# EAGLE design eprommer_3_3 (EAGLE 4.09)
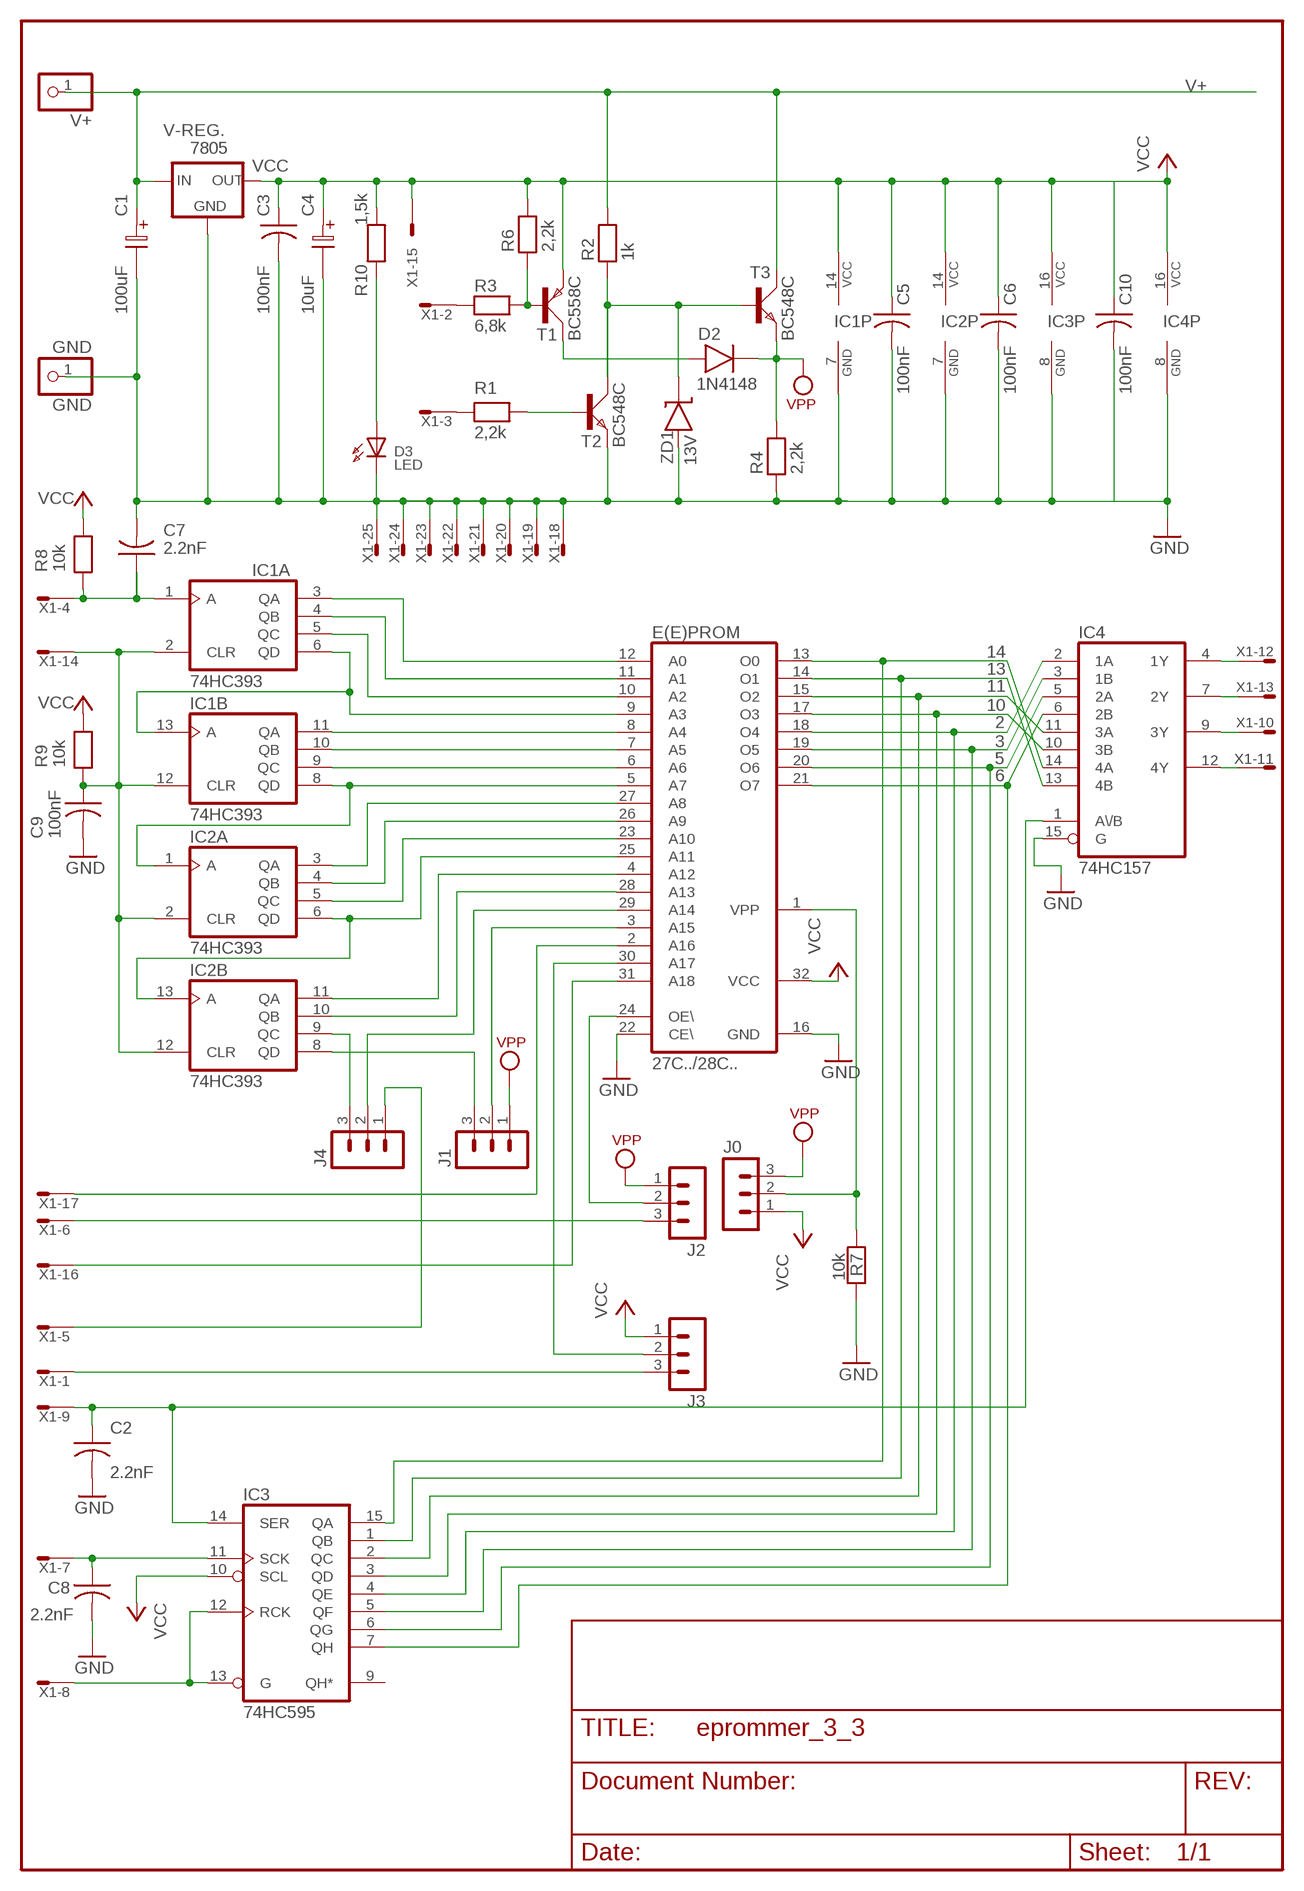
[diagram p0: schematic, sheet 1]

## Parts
C1  100uF  ELC-2,5  [ES-2,5]
C2  2.2nF  CAP-2,5  [C-2,5]
C3  100nF  CAP-2,5  [C-2,5]
C4  10uF  ELC-2,5  [ES-2,5]
C5  100nF  CAP-2,5  [C-2,5]
C6  100nF  CAP-2,5  [C-2,5]
C7  2.2nF  CAP-2,5  [C-2,5]
C8  2.2nF  CAP-2,5  [C-2,5]
C9  100nF  CAP-2,5  [C-2,5]
C10  100nF  CAP-2,5  [C-2,5]
D2  1N4148  DIODE-7,5  [D-7,5]
D3  LED  LED5  [LED5]
E(E)PROM  27C../28C..  27C4001D  [DIL32]
GND  GND  PINHD-1X1  [1X01]
IC1  74HC393  74393  [DIL14]
IC2  74HC393  74393  [DIL14]
IC3  74HC595  74595  [DIL16]
IC4  74HC157  74157  [DIL16]
J0  MA03-1  [MA03-1]
J1  MA03-1  [MA03-1]
J2  MA03-1  [MA03-1]
J3  MA03-1  [MA03-1]
J4  MA03-1  [MA03-1]
R1  2,2k  RESEU-7,5  [R-7,5]
R2  1k  RESEU-7,5  [R-7,5]
R3  6,8k  RESEU-7,5  [R-7,5]
R4  2,2k  RESEU-7,5  [R-7,5]
R6  2,2k  RESEU-7,5  [R-7,5]
R7  10k  RESEU-7,5  [R-7,5]
R8  10k  RESEU-7,5  [R-7,5]
R9  10k  RESEU-7,5  [R-7,5]
R10  1,5k  RESEU-7,5  [R-7,5]
T1  BC558C  BC557  [SOT54A]
T2  BC548C  BC547  [SOT54A]
T3  BC548C  BC547  [SOT54A]
V+  PINHD-1X1  [1X01]
V-REG.  7805  78XXS  [78XXS]
X1  M25HPS  [M25HP]
ZD1  13V  ZDIO-7,5  [D-7,5]

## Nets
A16: E(E)PROM.2(A16) X1.17(-17:M)
A17: J3.3 X1.1(-1:M)
A18/P: E(E)PROM.31(A18) X1.16(-16:M)
A/B_DATA: C2.1 IC3.14(SER) IC4.1(A\/B) X1.9(-9:M)
CLR_ADR: C9.1 IC1.2(A:CLR) IC1.12(B:CLR) IC2.2(A:CLR) IC2.12(B:CLR) R9.1 X1.14(-14:M)
D2/D3: IC4.7(2Y) X1.13(-13:M)
GND: C1.2 C2.2 C3.2 C4.2 C5.2 C6.2 C7.2 C8.2 C9.2 C10.2 D3.K E(E)PROM.16(GND) E(E)PROM.22(CE\) GND.1 IC1.7(P:GND) IC2.7(P:GND) IC3.8(GND) IC4.8(GND) IC4.15(G) R4.1 R7.1 T2.E V-REG..GND X1.18(-18:M) X1.19(-19:M) X1.20(-20:M) X1.21(-21:M) X1.22(-22:M) X1.23(-23:M) X1.24(-24:M) X1.25(-25:M) ZD1.1(A)
IC: E(E)PROM.8(A4) IC1.11(B:QA)
INC_ADR: C7.1 IC1.1(A:A) R8.1 X1.4(-4:M)
LOW->5V: R3.1 X1.2(-2:M)
LOW->12V: R1.1 X1.3(-3:M)
N$1: E(E)PROM.12(A0) IC1.3(A:QA)
N$2: E(E)PROM.11(A1) IC1.4(A:QB)
N$3: E(E)PROM.10(A2) IC1.5(A:QC)
N$4: E(E)PROM.9(A3) IC1.6(A:QD) IC1.13(B:A)
N$5: IC2.9(B:QC) J4.3
N$6: E(E)PROM.7(A5) IC1.10(B:QB)
N$7: E(E)PROM.6(A6) IC1.9(B:QC)
N$8: E(E)PROM.5(A7) IC1.8(B:QD) IC2.1(A:A)
N$9: E(E)PROM.27(A8) IC2.3(A:QA)
N$10: E(E)PROM.26(A9) IC2.4(A:QB)
N$11: E(E)PROM.23(A10) IC2.5(A:QC)
N$12: E(E)PROM.25(A11) IC2.6(A:QD) IC2.13(B:A)
N$13: E(E)PROM.4(A12) IC2.11(B:QA)
N$14: E(E)PROM.29(A14) J4.2
N$15: E(E)PROM.20(O6) IC3.6(QG) IC4.5(2A)
N$16: E(E)PROM.28(A13) IC2.10(B:QB)
N$17: IC2.8(B:QD) J1.3
N$18: E(E)PROM.30(A17) J3.2
N$19: R3.2 R6.1 T1.B
N$20: C8.1 IC3.11(SCK) X1.7(-7:M)
N$21: IC4.4(1Y) X1.12(-12:M)
N$22: IC4.12(4Y) X1.11(-11:M)
N$23: E(E)PROM.13(O0) IC3.15(QA) IC4.14(4A)
N$24: E(E)PROM.14(O1) IC3.1(QB) IC4.13(4B)
N$25: E(E)PROM.15(O2) IC3.2(QC) IC4.11(3A)
N$26: E(E)PROM.17(O3) IC3.3(QD) IC4.10(3B)
N$27: E(E)PROM.18(O4) IC3.4(QE) IC4.2(1A)
N$28: E(E)PROM.19(O5) IC3.5(QF) IC4.3(1B)
N$31: R1.2 T2.B
N$32: D2.1(A) T1.C
N$35: E(E)PROM.21(O7) IC3.7(QH) IC4.6(2B)
N$38: R2.1 T2.C T3.B ZD1.2(K)
N$46: D3.A R10.1
N$48: IC4.9(3Y) X1.10(-10:M)
N$49: E(E)PROM.24(OE\) J2.2
N$50: J2.3 X1.6(-6:M)
PGM: E(E)PROM.3(A15) J1.2
PGM/WE: J4.1 X1.5(-5:M)
RCK/G: IC3.12(RCK) IC3.13(G) X1.8(-8:M)
V+: C1.1 R2.2 T3.C V+.1 V-REG..IN
VCC: C3.1 C4.1 C5.1 C6.1 C10.1 E(E)PROM.32(VCC) IC1.14(P:VCC) IC2.14(P:VCC) IC3.10(SCL) IC3.16(VCC) IC4.16(VCC) J0.1 J3.1 R6.2 R8.2 R9.2 R10.2 T1.E V-REG..OUT X1.15(-15:M)
VPP: D2.2(K) J0.3 J1.1 J2.1 R4.2 T3.E
VPP_EP: E(E)PROM.1(VPP) J0.2 R7.2
Unconnected: IC3.9(QH*) X1.G1(-G:G1) X1.G2(-G:G2)

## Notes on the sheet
- 14
- 13
- 11
- 10
- 2
- 3
- 5
- 6

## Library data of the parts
C1 C4 = DISCRETE:ELC-2,5
C2 C3 C5-C10 = DISCRETE:CAP-2,5
D2 = DISCRETE:DIODE-7,5
D3 = LED:LED5
E(E)PROM = MEMNEC:27C4001D
GND V+ = PINHEAD:PINHD-1X1
IC1 IC2 = 74XX:74393
IC3 = 74XX:74595
IC4 = 74XX:74157
J0 J1-J4 = CON-LSTB:MA03-1
R1-R4 R6-R10 = DISCRETE:RESEU-7,5
T1 = TRANS-SM:BC557
T2 T3 = TRANS-SM:BC547
V-REG. = V-REG:78XXS
X1 = SUBD-A:M25HPS
ZD1 = DISCRETE:ZDIO-7,5

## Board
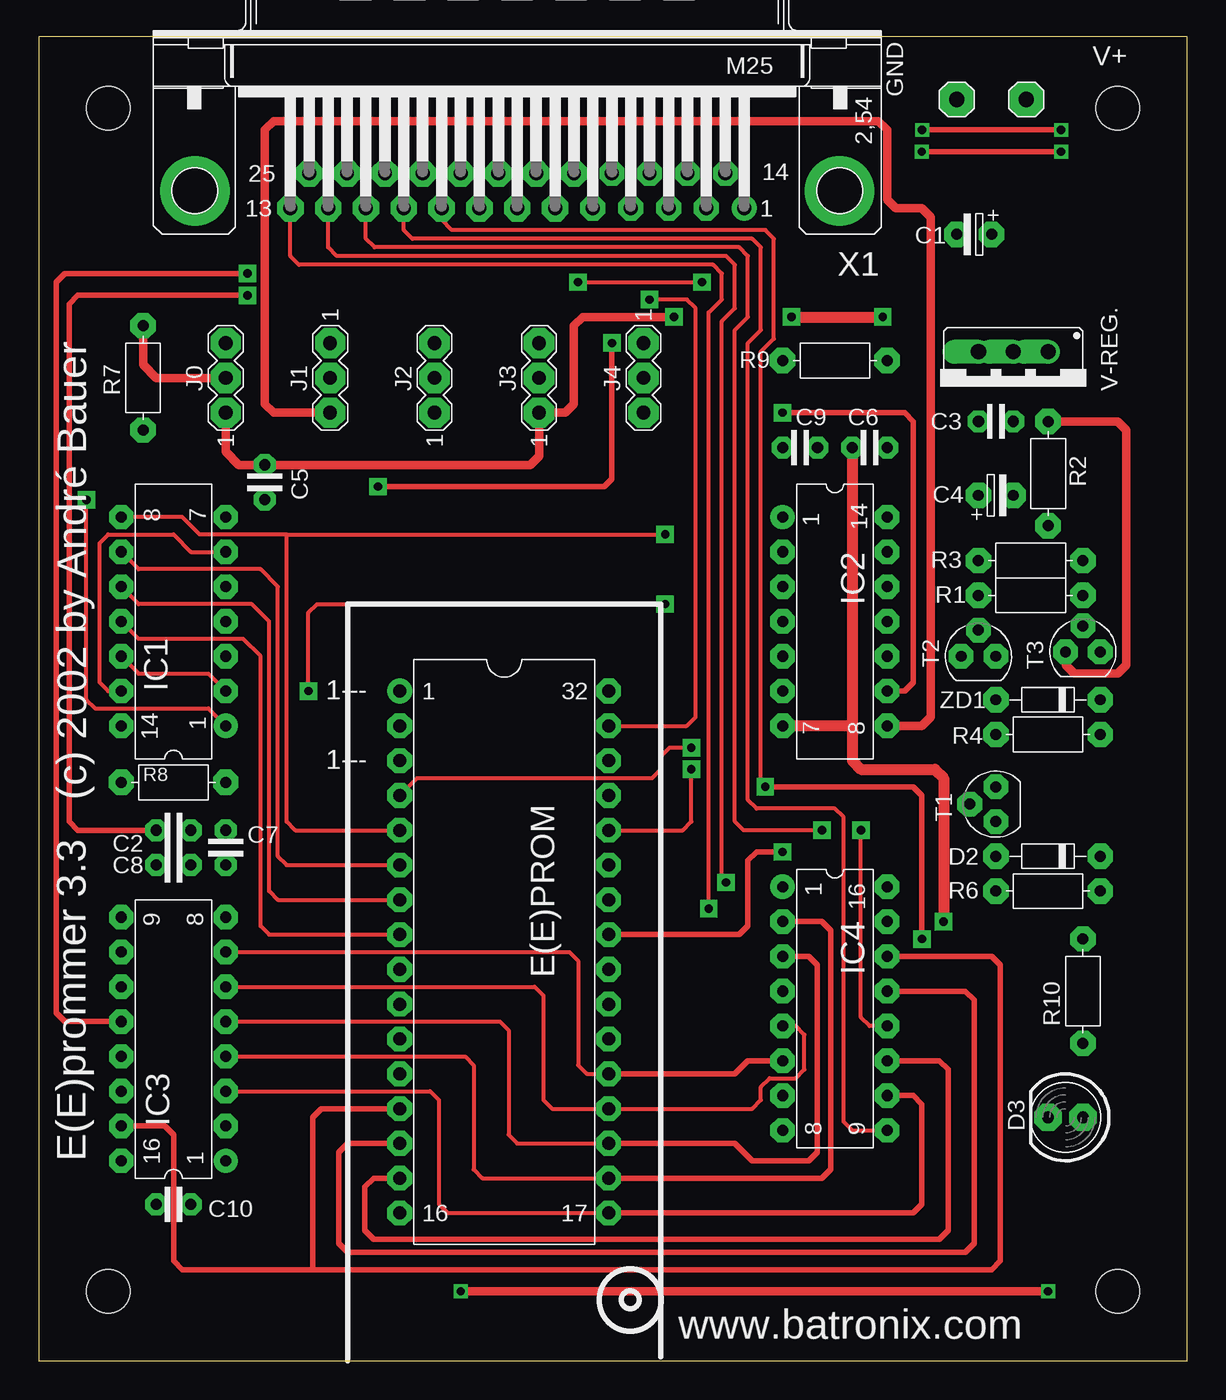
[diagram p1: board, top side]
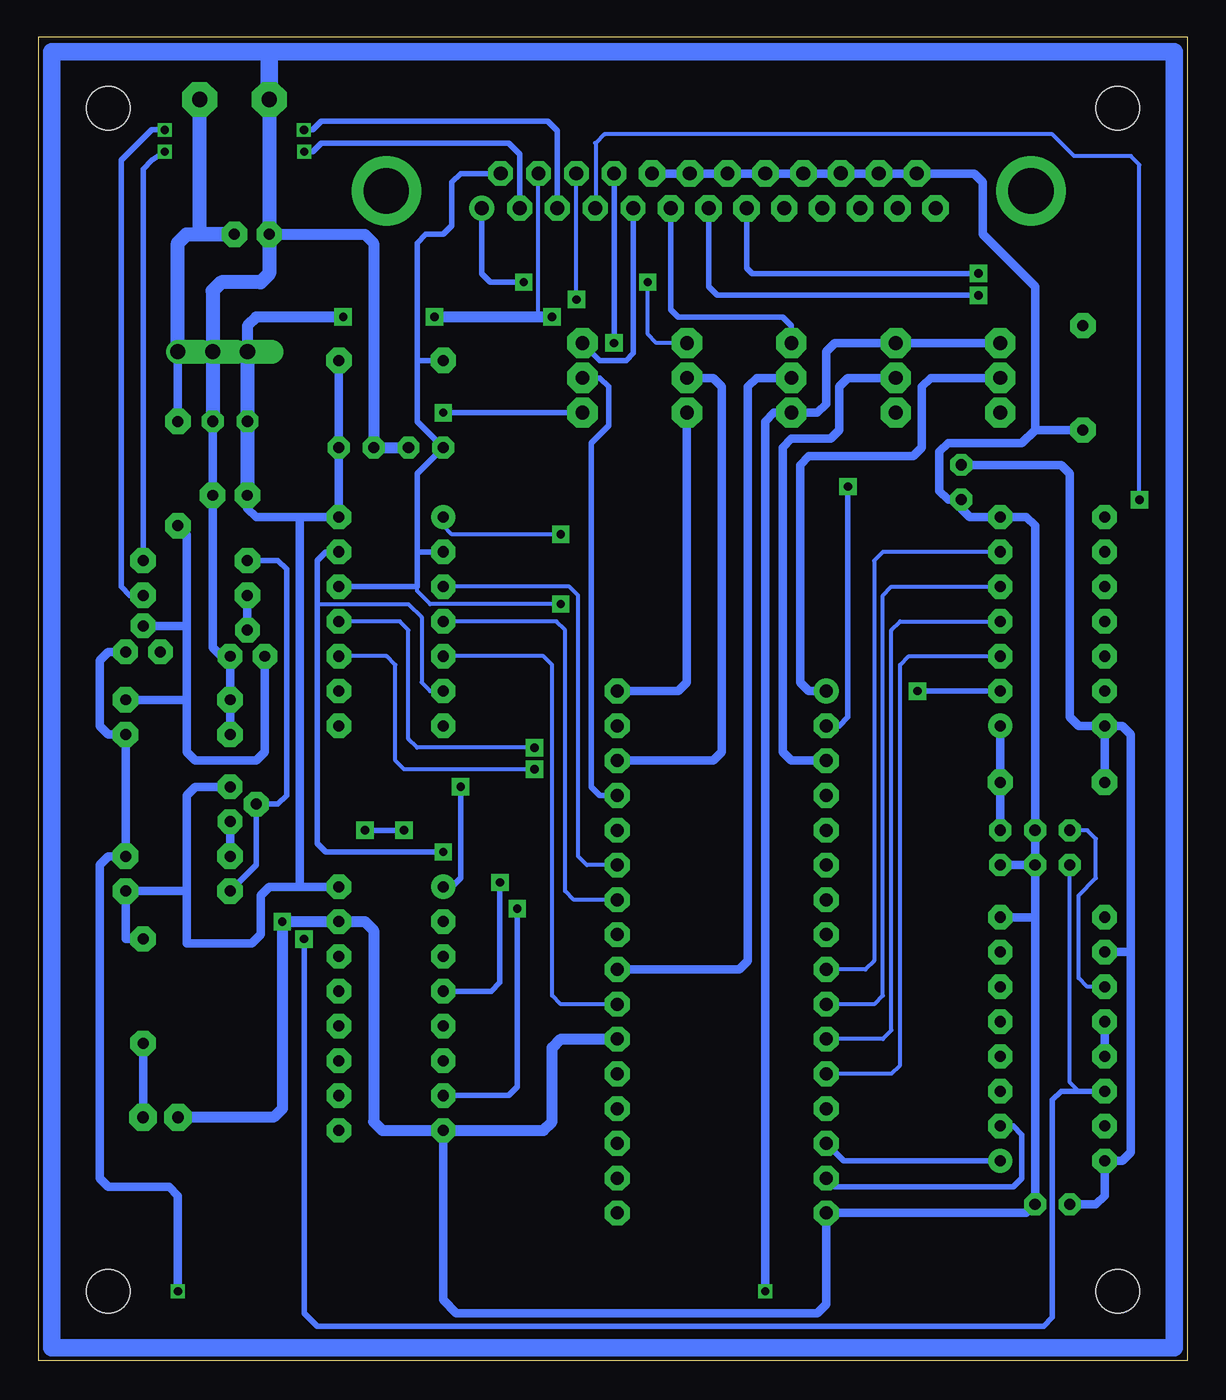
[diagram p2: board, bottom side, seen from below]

Size 83.82 x 96.67 mm. Coordinates in mm from the lower left corner, seen from the top.
Outline: 0,96.67 0,0 83.82,0 83.82,96.67 0,96.67
Copper layers used: Top, Bottom
Holes 3.2 mm at 5.08,91.43 78.73,91.43 5.08,5.07 78.73,5.07

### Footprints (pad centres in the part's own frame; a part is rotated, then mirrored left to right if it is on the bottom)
ES-2,5 = drill 0.8 pad 1.85 octagon: 1 -1.27,0; 2 1.27,0
C-2,5 = drill 0.813 pad 1.6 octagon: 1 -1.27,0; 2 1.27,0
D-7,5 = drill 0.8 pad 1.85 octagon: 1 -3.81,0; 2 3.81,0
LED5 = drill 0.85 pad 2 octagon: A -1.27,0; K 1.27,0
DIL32 = drill 0.95 pad 1.8 round: 1 -19.05,-7.62 | drill 0.95 pad 1.8 octagon: 2 -16.51,-7.62; 3 -13.97,-7.62; 4 -11.43,-7.62; 5 -8.89,-7.62; 6 -6.35,-7.62; 7 -3.81,-7.62; 8 -1.27,-7.62; 9 1.27,-7.62; 10 3.81,-7.62; 11 6.35,-7.62; 12 8.89,-7.62; 13 11.43,-7.62; 14 13.97,-7.62; 15 16.51,-7.62; 16 19.05,-7.62; 17 19.05,7.62; 18 16.51,7.62; 19 13.97,7.62; 20 11.43,7.62; 21 8.89,7.62; 22 6.35,7.62; 23 3.81,7.62; 24 1.27,7.62; 25 -1.27,7.62; 26 -3.81,7.62; 27 -6.35,7.62; 28 -8.89,7.62; 29 -11.43,7.62; 30 -13.97,7.62; 31 -16.51,7.62; 32 -19.05,7.62
1X01 = drill 1.016 pad 2.54 octagon: 1 0,0
DIL14 = drill 0.813 pad 1.778 round: 1 -7.62,-3.81 | drill 0.813 pad 1.778 octagon: 2 -5.08,-3.81; 3 -2.54,-3.81; 4 0,-3.81; 5 2.54,-3.81; 6 5.08,-3.81; 7 7.62,-3.81; 8 7.62,3.81; 9 5.08,3.81; 10 2.54,3.81; 11 0,3.81; 12 -2.54,3.81; 13 -5.08,3.81; 14 -7.62,3.81
DIL16 = drill 0.813 pad 1.778 round: 1 -8.89,-3.81 | drill 0.813 pad 1.778 octagon: 2 -6.35,-3.81; 3 -3.81,-3.81; 4 -1.27,-3.81; 5 1.27,-3.81; 6 3.81,-3.81; 7 6.35,-3.81; 8 8.89,-3.81; 9 8.89,3.81; 10 6.35,3.81; 11 3.81,3.81; 12 1.27,3.81; 13 -1.27,3.81; 14 -3.81,3.81; 15 -6.35,3.81; 16 -8.89,3.81
MA03-1 = drill 1 pad 2.2 octagon: 1 -2.54,0; 2 0,0; 3 2.54,0
R-7,5 = drill 0.8 pad 1.85 octagon: 1 -3.81,0; 2 3.81,0
SOT54A = drill 0.8 pad 1.8 octagon: B 0,1.905; C -1.27,0; E 1.27,0
78XXS = drill 1.1 pad 1.75 offset: GND 0,-2.54; IN -2.54,-2.54; OUT 2.54,-2.54
M25HP = drill 1.016 pad 1.8 round: 1 -16.561,1.27 | drill 1.016 pad 1.8 octagon: 2 -13.792,1.27; 3 -11.049,1.27; 4 -8.28,1.27; 5 -5.512,1.27; 6 -2.769,1.27; 7 0,1.27; 8 2.769,1.27; 9 5.512,1.27; 10 8.28,1.27; 11 11.049,1.27; 12 13.792,1.27; 13 16.561,1.27; 14 -15.189,-1.27; 15 -12.421,-1.27; 16 -9.652,-1.27; 17 -6.909,-1.27; 18 -4.14,-1.27; 19 -1.372,-1.27; 20 1.372,-1.27; 21 4.14,-1.27; 22 6.909,-1.27; 23 9.652,-1.27; 24 12.421,-1.27; 25 15.189,-1.27 | drill 3.302 pad 5.08 round: G1 -23.52,0; G2 23.52,0

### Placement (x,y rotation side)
C1  68.26,82.23 180 top
C2  9.84,36.19 0 top
C3  69.84,68.57 0 top
C4  69.84,63.18 0 top
C5  16.5,64.13 270 top
C6  60.64,66.67 180 top
C7  13.65,37.46 270 top
C8  9.84,38.73 0 top
C9  55.56,66.67 0 top
C10  9.84,11.42 0 top
D2  73.66,36.82 0 top
D3  74.92,17.77 180 top
E(E)PROM  33.97,29.84 270 top
GND  66.99,92.07 0 top
IC1  9.84,53.97 90 top
IC2  58.1,53.97 270 top
IC3  9.84,23.49 90 top
IC4  58.1,25.71 270 top
J0  13.65,71.75 90 top
J1  21.27,71.75 270 top
J2  28.89,71.75 90 top
J3  36.51,71.75 90 top
J4  44.13,71.75 270 top
R1  72.38,55.87 180 top
R2  73.66,64.76 90 top
R3  72.38,58.41 180 top
R4  73.66,45.71 0 top
R6  73.66,34.28 0 top
R7  7.62,71.75 90 top
R8  9.84,42.22 180 top
R9  58.1,73.02 0 top
R10  76.19,26.98 90 top
T1  69.84,40.63 90 top
T2  68.57,51.43 0 top
T3  76.19,51.75 0 top
V+  72.07,92.07 0 top
V-REG.  71.11,71.11 180 top
X1  34.92,85.4 180 top
ZD1  73.66,48.25 0 top

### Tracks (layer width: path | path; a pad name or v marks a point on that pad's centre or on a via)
A16  (via drill 0.61 pad 1.27)
  Top 0.406: v24.76,63.81 41.27,63.81 41.83,64.37 v41.83,74.29
  Bottom 0.406: v41.83,74.29 X1.17 | v24.76,63.81 24.76,46.98 25.4,46.35 E(E)PROM.2
A17  (via drill 0.61 pad 1.27)
  Top 0.305: v39.37,78.74 v48.41,78.74
  Bottom 0.305: J3.3 38.73,74.29 39.37,74.93 v39.37,78.74
  Bottom 0.406: v48.41,78.74 50.85,78.74 51.48,79.37 X1.1
A18/P  (via drill 0.61 pad 1.27)
  Top 0.305: v44.57,77.46 47.3,77.46 47.94,76.83 47.94,46.98 47.3,46.35 E(E)PROM.31
  Bottom 0.305: v44.57,77.46 X1.16
A/B_DATA  (via drill 0.61 pad 1.27, 1.02 pad 1.93)
  Top 0.305: X1.9 29.42,84.45 29.42,83.28 30.16,82.55 53.02,82.55 53.65,81.91 53.65,74.61 52.7,73.66 52.7,42.22 v53.02,41.9
  Top 0.406: v64.45,30.79 64.45,41.27 63.81,41.9 v53.02,41.9
  Bottom 0.305: C2.1 8.57,20.31 7.93,19.68
  Bottom 0.406: IC4.1 53.65,34.6 53.02,35.24 v53.02,41.9 | IC3.14 7.93,19.68 9.2,19.68 9.84,19.04 9.84,3.17 10.47,2.53 63.5,2.53 64.45,3.49 v64.45,30.79
  other vias: 29.41,84.13
CLR_ADR  (via drill 0.61 pad 1.27)
  Top 0.305: IC1.12 7.3,50.16 12.38,50.16 IC1.2 | v45.72,55.24 20.31,55.24 19.68,54.61 v19.68,48.89
  Bottom 0.305: v45.72,55.24 55.24,55.24 56.19,56.19 56.19,56.51
  Bottom 0.406: X1.14 53.02,86.67 53.65,86.04 53.65,82.86 54.29,82.23 55.56,82.23 56.19,81.59 56.19,73.02 | 56.19,59.05 56.19,64.77 C9.1 56.19,68.57 56.19,73.02 | 56.19,59.05 IC2.2 | 56.19,59.05 56.19,56.51 IC2.12 | IC1.2 v19.68,48.89 | 56.19,73.02 R9.1
D2/D3  (via drill 0.61 pad 1.27, 1.02 pad 1.93)
  Top 0.305: X1.13 18.36,80.64 18.99,80.01 49.21,80.01 49.84,79.37 49.84,77.46 48.89,76.51 v48.89,33.01
  Bottom 0.406: IC4.7 49.52,19.36 48.89,20 v48.89,33.01
  other vias: 18.36,84.13
GND  (via drill 0.61 pad 1.27, 1.02 pad 1.93, 1.1 pad 2.54)
  Top 0.813: C6.2 59.37,46.35 | v66.04,32.06 66.04,42.54 65.4,43.18 60,43.18 59.37,43.81 59.37,46.35 | 59.37,46.35 IC2.7
  Bottom 0.305: IC4.15 61.91,31.75 | IC4.8 53.97,16.82
  Bottom 0.406: 69.53,51.11 T2.E ZD1.1
  Bottom 0.61: C3.2 C4.2 71.12,52.07 70.48,51.43 T2.E ZD1.1 R4.1 | v22.5,86.67 22.54,86.99 | v22.5,86.67 v19.73,86.67 15.55,86.67 14.92,86.04 14.92,82.23 11.11,78.42 11.11,67.94 | v25.27,86.67 v25.27,86.68 | v22.5,86.67 v25.27,86.67 | v25.27,86.67 v28.01,86.67 X1.21 | X1.21 v30.78,86.67 | v33.55,86.67 33.65,86.99 | X1.21 v33.55,86.67 | v33.55,86.67 v36.29,86.67 v39.06,86.67 | IC4.8 54.29,4.44 53.33,3.49 26.98,3.49 26.35,4.12 E(E)PROM.16 11.74,10.79 C10.2 11.11,32.38 | 11.11,32.38 IC3.8 | 11.11,32.38 C2.2 | C2.2 C8.2 | C8.2 11.11,60.96 11.74,61.59 IC1.7 | IC1.7 13.33,61.91 | IC1.7 15.87,61.59 16.51,62.22 C5.2 17.46,62.86 18.09,63.5 18.09,66.35 17.46,66.99 12.06,66.99 11.11,67.94 | C2.2 C8.2 | C2.2 C7.2 | 11.11,67.94 R7.1 | C2.2 C8.2
  Bottom 0.813: E(E)PROM.22 45.72,23.49 46.35,22.85 46.35,17.46 46.98,16.82 IC4.8 58.73,16.82 59.37,17.46 59.37,31.43 60,32.06 IC4.15 v66.04,32.06 66.04,18.41 66.67,17.78 D3.K | C1.2 60,82.23 59.37,81.59 C6.2 C9.2
  Bottom 1.016: C3.2 V-REG..GND 71.12,78.1 70.48,78.74 67.62,78.74 66.99,79.37 C1.2 GND.1
  Bottom 1.27: 66.99,95.56 82.86,95.56 82.86,0.95 0.95,0.95 0.95,95.56 66.99,95.56 | 66.99,95.56 GND.1
  other vias: 66.99,92.07
IC
  Top 0.305: IC1.11 7.3,52.7 14.92,52.7 16.19,51.43 16.19,31.75 16.82,31.11 E(E)PROM.8
INC_ADR  (via drill 0.61 pad 1.27)
  Top 0.305: v3.49,62.86 3.49,48.26 4.12,47.62 12.38,47.62 IC1.1
  Bottom 0.305: 43.18,88.9 42.54,89.53 9.84,89.53 8.25,87.94 4.12,87.94 3.49,87.31 v3.49,62.86 | X1.4 43.18,84.13 43.18,88.9 | 43.18,88.9 43.2,88.9
  Bottom 0.406: R8.1 C7.1
  Bottom 0.61: IC1.1 R8.1 C7.1
LOW->5V  (via drill 0.61)
  Top 0.406: v64.43,88.26 v74.61,88.26
  Bottom 0.406: v64.43,88.26 63.81,88.26 63.18,88.9 49.52,88.9 48.71,88.09 X1.2 | v74.61,88.26 75.56,87.63 76.19,86.99 R3.1
LOW->12V  (via drill 0.61)
  Top 0.406: v64.46,89.85 v74.61,89.85
  Bottom 0.406: R1.1 77.15,55.87 77.78,56.51 77.78,87.63 75.56,89.85 v74.61,89.85 | v64.46,89.85 63.81,89.85 63.18,90.48 46.67,90.48 45.97,89.78 X1.3
N$1
  Bottom 0.305: IC1.3 20.31,51.43 20.95,50.79 20.95,21.58 21.58,20.95 E(E)PROM.12
N$2
  Bottom 0.305: IC1.4 20.95,53.97 21.58,53.33 21.58,24.13 22.22,23.49 E(E)PROM.11
N$3
  Bottom 0.305: IC1.5 21.58,56.51 22.22,55.87 22.22,26.67 22.85,26.03 E(E)PROM.10
N$4
  Top 0.305: IC1.13 5.07,48.89 4.44,49.52 4.44,59.69 5.07,60.32 9.84,60.32 11.11,59.05 IC1.6
  Bottom 0.305: IC1.6 22.22,59.05 22.85,58.41 22.85,29.2 23.49,28.57 E(E)PROM.9
N$5  (via drill 0.61 pad 1.27)
  Top 0.406: v54.29,69.21 63.18,69.21 63.81,68.57 63.81,49.52 63.18,48.89 IC2.9
  Bottom 0.406: v54.29,69.21 J4.3
N$6
  Top 0.305: IC1.10 7.3,55.24 15.55,55.24 16.82,53.97 16.82,34.29 17.46,33.65 E(E)PROM.7
N$7
  Top 0.305: IC1.9 7.3,57.78 16.19,57.78 17.46,56.51 17.46,36.83 18.09,36.19 E(E)PROM.6
N$8  (via drill 0.61 pad 1.27)
  Top 0.305: IC1.8 10.47,61.59 11.74,60.32 18.09,60.32 | 18.09,60.32 18.09,39.37 18.73,38.73 E(E)PROM.5 | 18.09,60.32 v45.72,60.32
  Bottom 0.305: v45.72,60.32 53.65,60.32 54.29,60.96 IC2.1
N$9
  Bottom 0.305: IC2.3 45.08,56.51 44.44,55.87 44.44,36.83 43.81,36.19 E(E)PROM.27
N$10
  Bottom 0.305: IC2.4 46.03,53.97 45.4,53.33 45.4,34.29 44.76,33.65 E(E)PROM.26
N$11
  Bottom 0.305: IC2.5 46.98,51.43 46.35,50.79 46.35,26.67 45.72,26.03 E(E)PROM.23
N$12  (via drill 0.61 pad 1.27)
  Top 0.406: E(E)PROM.25 51.11,31.11 51.75,31.75 51.75,36.51 52.38,37.14 v54.29,37.14
  Bottom 0.305: IC2.6 55.24,48.89 55.87,49.52 55.87,54.29 56.83,55.24 63.5,55.24
  Bottom 0.406: v54.29,37.14 62.86,37.14 63.5,37.78 63.5,55.24 63.5,58.41 62.86,59.05 IC2.13
N$13  (via drill 0.61 pad 1.27)
  Top 0.305: v47.62,44.76 46.03,44.76 45.4,44.13 45.4,43.18 44.76,42.54 27.62,42.54 E(E)PROM.4
  Bottom 0.305: IC2.11 57.46,53.97 56.83,53.33 56.83,45.4 56.19,44.76 v47.62,44.76
N$14
  Bottom 0.406: J4.2 42.86,71.75 42.22,71.12 42.22,68.26 43.49,66.99 43.49,41.9 42.86,41.27 E(E)PROM.29
N$15
  Top 0.305: IC3.6 36.19,27.3 36.83,26.67 36.83,19.04 37.46,18.41 E(E)PROM.20 52.07,18.41 52.7,19.04 52.7,20 53.33,20.63 55.24,20.63 55.87,21.27 55.87,23.81 55.24,24.44 IC4.5
N$16  (via drill 0.61 pad 1.27)
  Top 0.305: v47.62,43.18 47.62,39.37 46.98,38.73 E(E)PROM.28
  Bottom 0.305: IC2.10 58.41,51.43 57.78,50.79 57.78,43.81 57.15,43.18 v47.62,43.18
N$17
  Top 0.61: IC2.8 64.45,46.35 65.08,46.98 65.08,83.5 64.45,84.13 62.54,84.13 61.91,84.77 61.91,89.85 61.27,90.48 17.14,90.48 16.51,89.85 16.51,69.85 17.14,69.21 J1.3
N$18
  Bottom 0.61: J3.2 34.6,71.75 33.97,71.12 33.97,44.44 34.6,43.81 E(E)PROM.30
N$19
  Bottom 0.406: R3.2 66.35,58.41 65.72,57.78 65.72,41.27 66.35,40.64 T1.B 67.94,36.19 R6.1
N$20  (via drill 0.61 pad 1.27, 1.02 pad 1.93)
  Top 0.406: v15.23,77.78 2.85,77.78 2.22,77.15 2.22,39.37 2.85,38.73 C8.1
  Bottom 0.305: C8.1 7.3,38.73 6.66,38.09 6.66,35.24 7.93,33.97 7.93,27.94 7.3,27.3 IC3.11
  Bottom 0.406: X1.7 34.92,78.42 34.29,77.78 v15.23,77.78
  other vias: 34.92,84.13
N$21  (via drill 0.61 pad 1.27, 1.02 pad 1.93)
  Top 0.305: X1.12 21.13,81.27 21.76,80.64 50.16,80.64 50.79,80.01 50.79,76.83 49.84,75.88 49.84,34.92 v50.16,34.92
  Bottom 0.406: IC4.4 50.79,26.98 50.16,27.62 v50.16,34.92
  other vias: 21.13,84.13
N$22  (via drill 0.61 pad 1.27, 1.02 pad 1.93)
  Top 0.305: IC4.12 60.64,24.44 60,25.08 v60,38.73 | X1.11 23.87,81.91 24.51,81.27 51.11,81.27 51.75,80.64 51.75,76.19 50.79,75.24 50.79,39.37 51.43,38.73 v57.15,38.73
  Bottom 0.406: v60,38.73 v57.15,38.73
  other vias: 23.87,84.13
N$23
  Top 0.406: 20,6.66 69.53,6.66 70.16,7.3 70.16,28.89 69.53,29.52 IC4.14 | E(E)PROM.13 20.63,18.41 20,17.78 20,6.66 | 20,6.66 10.47,6.66 9.84,7.3 9.84,16.51 9.2,17.14 IC3.15
N$24
  Top 0.406: E(E)PROM.14 22.54,15.87 21.9,15.23 21.9,8.57 22.54,7.93 67.62,7.93 68.26,8.57 68.26,26.35 67.62,26.98 IC4.13
  Bottom 0.406: E(E)PROM.14 25.08,14.6 IC3.1
N$25
  Top 0.406: E(E)PROM.15 24.44,13.33 23.81,12.7 23.81,9.52 24.44,8.88 65.72,8.88 66.35,9.52 66.35,21.27 65.72,21.9 IC4.11
  Bottom 0.406: E(E)PROM.15 25.71,12.7 12.7,12.7 12.06,13.33 12.06,16.51 12.7,17.14 IC3.2
N$26
  Top 0.305: IC3.3 28.57,19.68 29.2,19.04 29.2,11.43 29.84,10.79 E(E)PROM.17
  Top 0.406: E(E)PROM.17 63.81,10.79 64.45,11.43 64.45,18.73 63.81,19.36 IC4.10
N$27
  Top 0.305: IC3.4 31.11,22.22 31.75,21.58 31.75,13.96 32.38,13.33 E(E)PROM.18
  Top 0.406: E(E)PROM.18 57.15,13.33 57.78,13.96 57.78,31.43 57.15,32.06 IC4.2
N$28
  Top 0.305: E(E)PROM.19 34.92,15.87 34.29,16.51 34.29,24.13 33.65,24.76 IC3.5
  Top 0.406: E(E)PROM.19 50.79,15.87 52.07,14.6 56.19,14.6 56.83,15.23 56.83,28.89 56.19,29.52 IC4.3
N$31
  Bottom 0.61: T2.B R1.2
N$32
  Bottom 0.61: D2.1 T1.C
N$35
  Top 0.305: E(E)PROM.21 40,20.95 39.37,21.58 39.37,29.2 38.73,29.84 IC3.7
  Top 0.406: E(E)PROM.21 50.79,20.95 51.75,21.9 IC4.6
N$38
  Bottom 0.406: 73.02,60.32 R2.1
  Bottom 0.61: 73.02,53.65 73.02,60.32 | 73.02,48.26 73.02,53.65 | 73.02,53.65 T3.B | 73.02,48.26 73.02,44.44 72.38,43.81 67.94,43.81 67.3,44.44 T2.C | 73.02,48.26 ZD1.2
N$46
  Bottom 0.61: R10.1 D3.A
N$48  (via drill 1.02 pad 1.93)
  Top 0.305: IC4.9 59.37,16.82 58.73,17.46 58.73,39.68 58.1,40.32 52.38,40.32 51.75,40.95 51.75,74.29 52.7,75.24 52.7,81.27 52.07,81.91 27.27,81.91 26.64,82.55 X1.10
  other vias: 26.64,84.13
N$49
  Bottom 0.61: J2.2 31.43,71.75 32.06,71.12 32.06,29.2 32.7,28.57 E(E)PROM.24
N$50  (via drill 1.02 pad 1.93)
  Bottom 0.406: X1.6 37.69,76.74 37.14,76.19 29.52,76.19 28.89,75.56 J2.3
  other vias: 37.69,84.13
PGM
  Bottom 0.61: J1.2 24.76,71.75 25.4,71.12 25.4,67.94 26.03,67.3 28.89,67.3 29.52,66.67 29.52,44.44 28.89,43.81 E(E)PROM.3
PGM/WE
  Bottom 0.406: X1.5 40.43,73.54 40.95,73.02 42.86,73.02 J4.1
RCK/G  (via drill 0.61 pad 1.27, 1.02 pad 1.93)
  Top 0.406: v15.23,79.37 1.9,79.37 1.26,78.74 1.26,25.4 1.9,24.76 IC3.12
  Bottom 0.406: v15.23,79.37 31.75,79.37 32.15,79.78 X1.8
  Bottom 0.61: IC3.12 IC3.13
  other vias: 32.15,84.13
V+  (via drill 1.1 pad 2.54)
  Top 0.61: R2.2 78.74,68.57 79.37,67.94 79.37,50.79 78.74,50.16 75.56,50.16 74.93,50.79 T3.C
  Bottom 0.61: R2.2 V-REG..IN
  Bottom 1.016: V+.1 72.07,82.23 C1.1 73.02,82.23 73.66,81.59 V-REG..IN
  other vias: 72.07,92.07
VCC  (via drill 0.61 pad 1.27)
  Top 0.61: v46.35,76.19 39.68,76.19 39.05,75.56 39.05,69.85 38.41,69.21 J3.1 36.51,66.04 35.87,65.4 C5.1 14.6,65.4 13.65,66.35 J0.1
  Top 0.813: v54.92,76.19 v61.59,76.19
  Bottom 0.305: 47.34,76.19 X1.15
  Bottom 0.61: 73.02,34.29 73.02,30.47 68.26,30.47 67.62,31.11 67.62,33.97 66.99,34.6 64.77,34.6 | 73.02,34.29 73.02,41.27 72.38,41.9 T1.E | C4.1 68.57,62.22 67.94,61.59 64.77,61.59 | 64.77,61.59 IC2.14 | 64.77,61.59 64.77,34.6 | IC2.14 C6.1 | C6.1 R9.2 | 64.77,34.6 IC4.16 | C5.1 9.2,65.4 8.57,64.77 8.57,46.98 7.93,46.35 IC1.14 | IC1.14 4.76,46.35 4.12,45.72 4.12,29.84 | 4.12,29.84 4.12,15.23 4.76,14.6 IC3.16 6.03,12.06 6.66,11.43 C10.1 | 4.12,29.84 IC3.10 | J3.1 36.51,49.52 37.14,48.89 E(E)PROM.32 | 73.02,34.29 R6.2 77.46,30.79 R10.2 | IC1.14 R8.2 | IC2.14 C6.1
  Bottom 0.813: v46.35,76.19 47.34,76.19 v54.92,76.19 | v61.59,76.19 67.94,76.19 68.57,75.56 V-REG..OUT
  Bottom 1.016: V-REG..OUT C3.1 C4.1
VPP  (via drill 0.61 pad 1.02)
  Top 0.61: v30.79,5.07 v73.66,5.07
  Bottom 0.61: T3.E 78.74,51.75 79.37,51.11 79.37,46.35 78.74,45.72 R4.2 D2.2 78.74,36.83 79.37,36.19 79.37,13.33 78.74,12.7 74.29,12.7 73.66,12.06 v73.66,5.07 | v30.79,5.07 30.79,68.57 30.16,69.21 J2.1 26.98,69.21 26.35,69.85 26.35,73.66 25.71,74.29 J1.1 J0.3
VPP_EP
  Top 0.61: R7.2 7.62,72.7 8.57,71.75 J0.2
  Bottom 0.61: E(E)PROM.1 27.62,48.89 28.25,49.52 28.25,65.4 27.62,66.04 20,66.04 19.36,66.67 19.36,71.12 18.73,71.75 J0.2

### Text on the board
tPlace: 1--- | 1--- | (c) 2002 by André Bauer | E(E)prommer 3.3 | www.batronix.com
tValues: 2*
